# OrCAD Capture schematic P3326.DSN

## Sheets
1 03_Front Camera Connector: size Custom
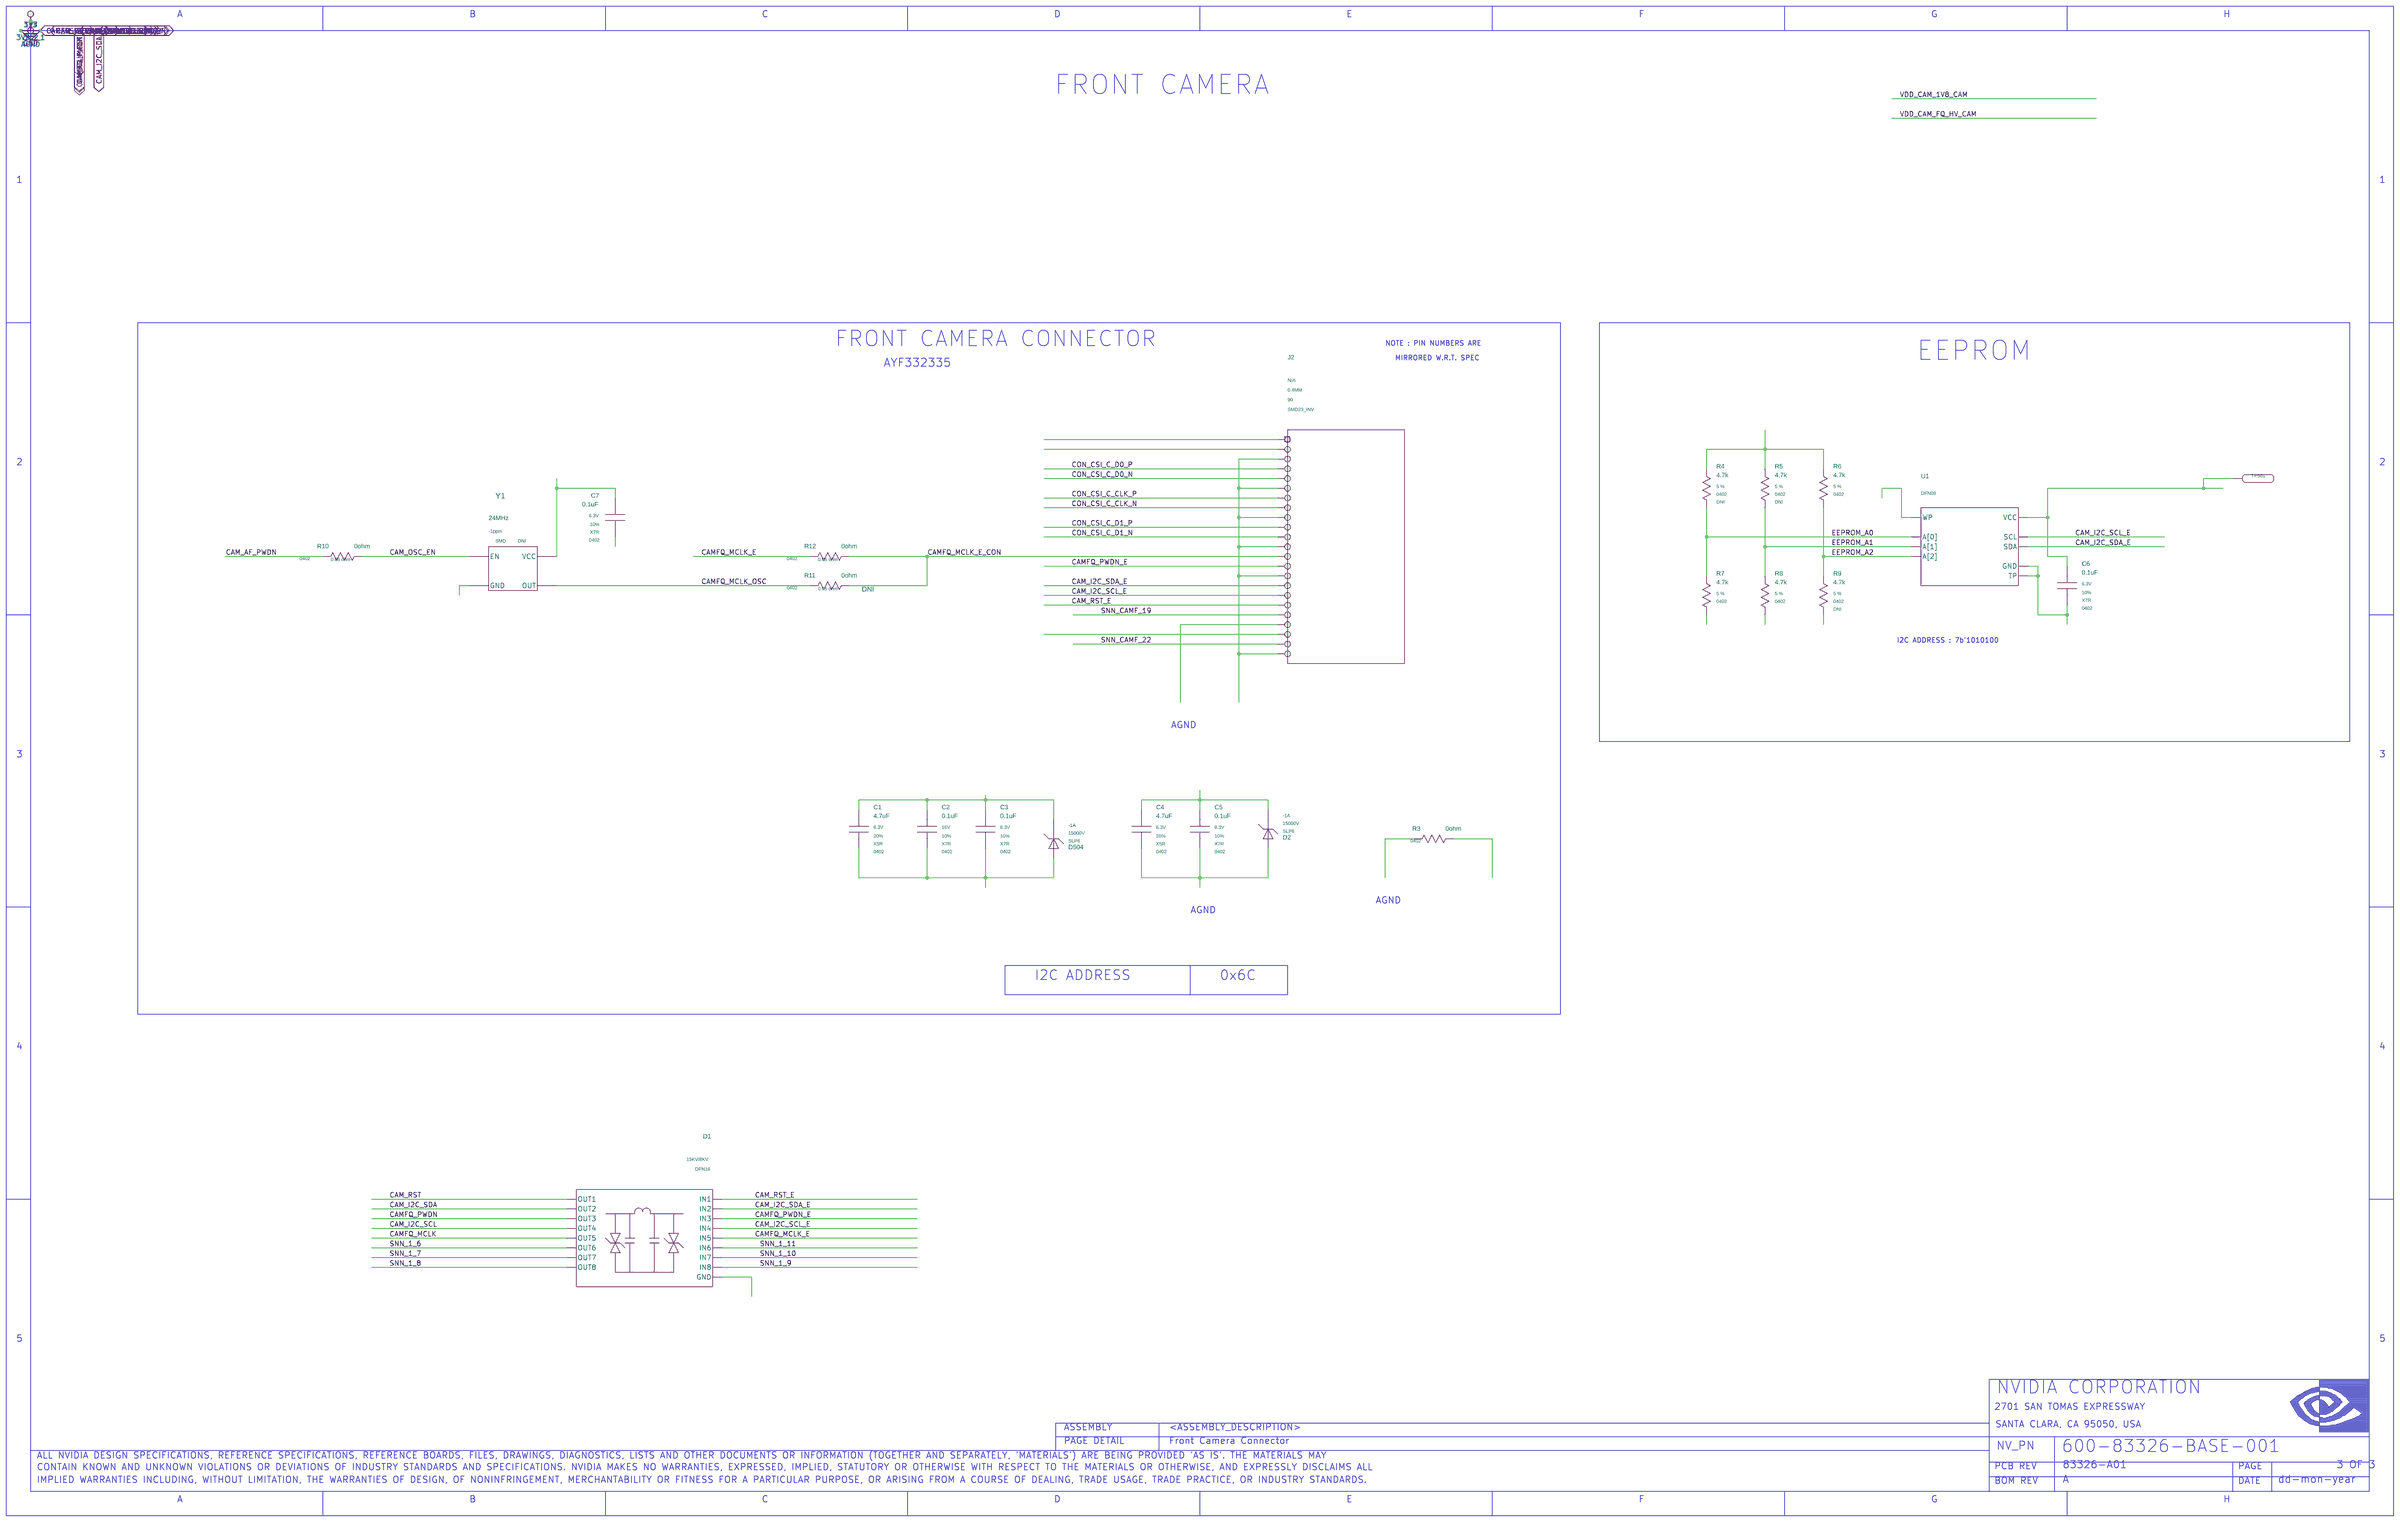
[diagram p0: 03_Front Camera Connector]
2 02_BTB Connector: size Custom
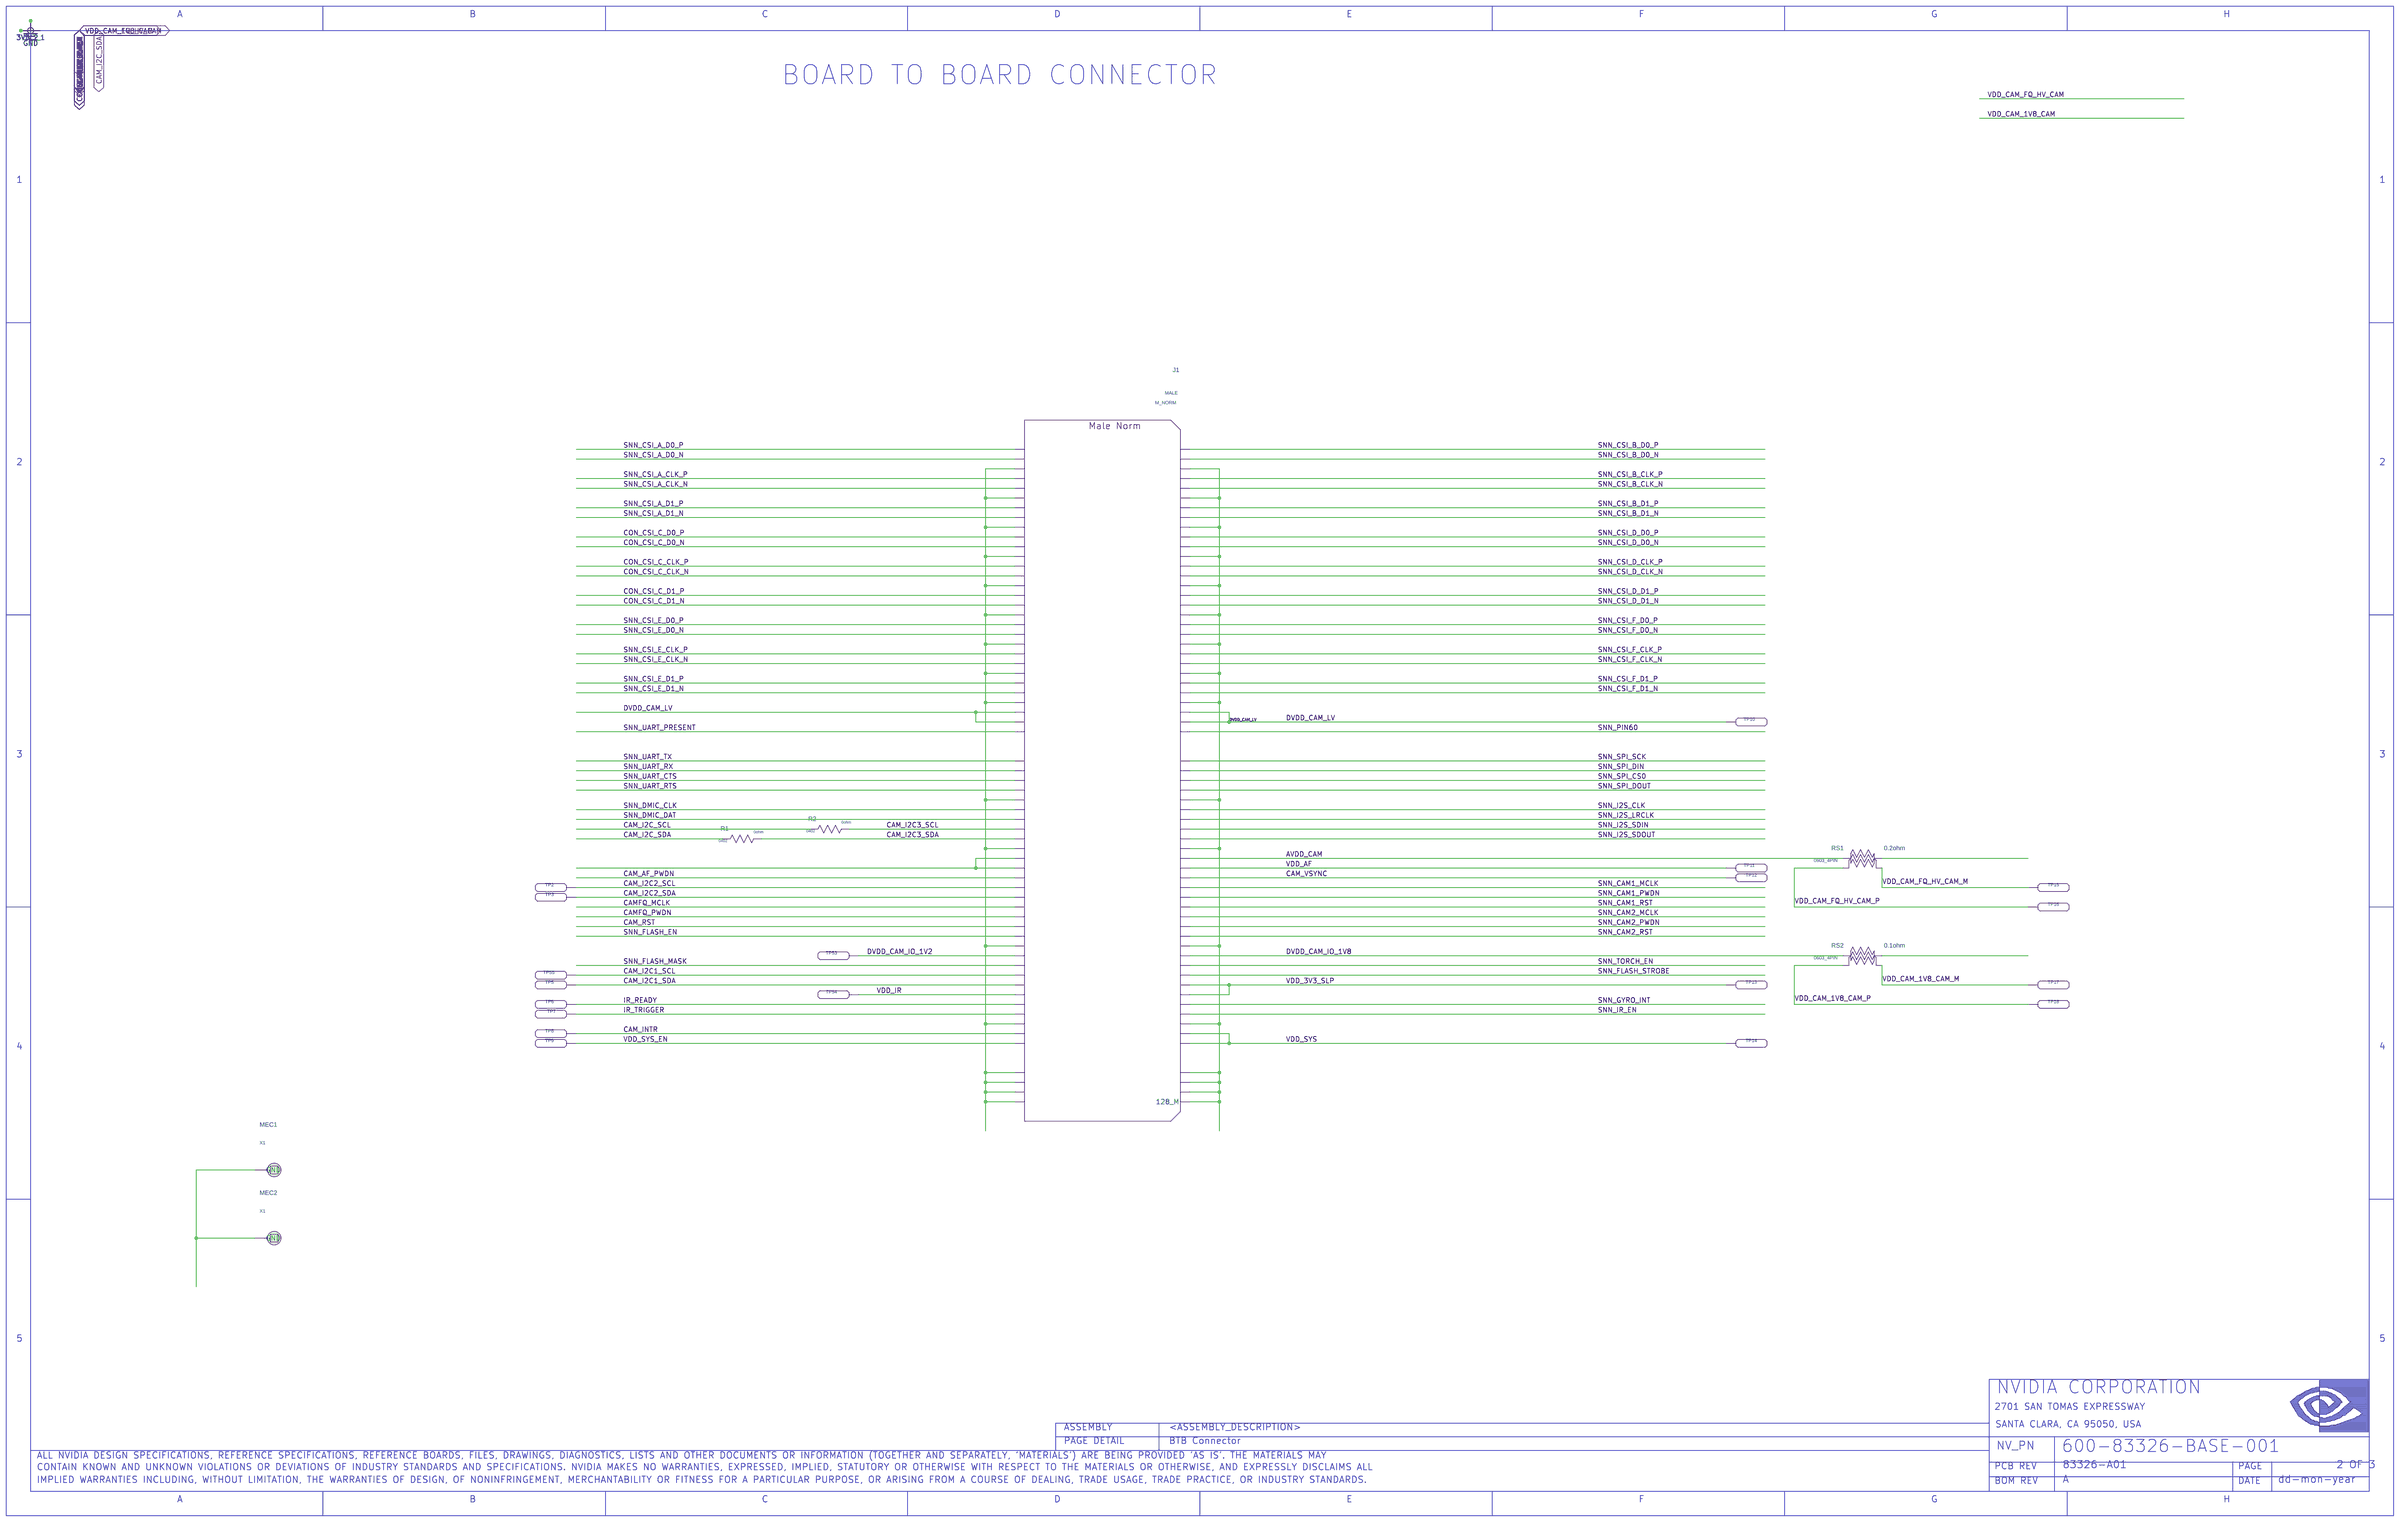
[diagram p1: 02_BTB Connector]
3 01_Table of Contents
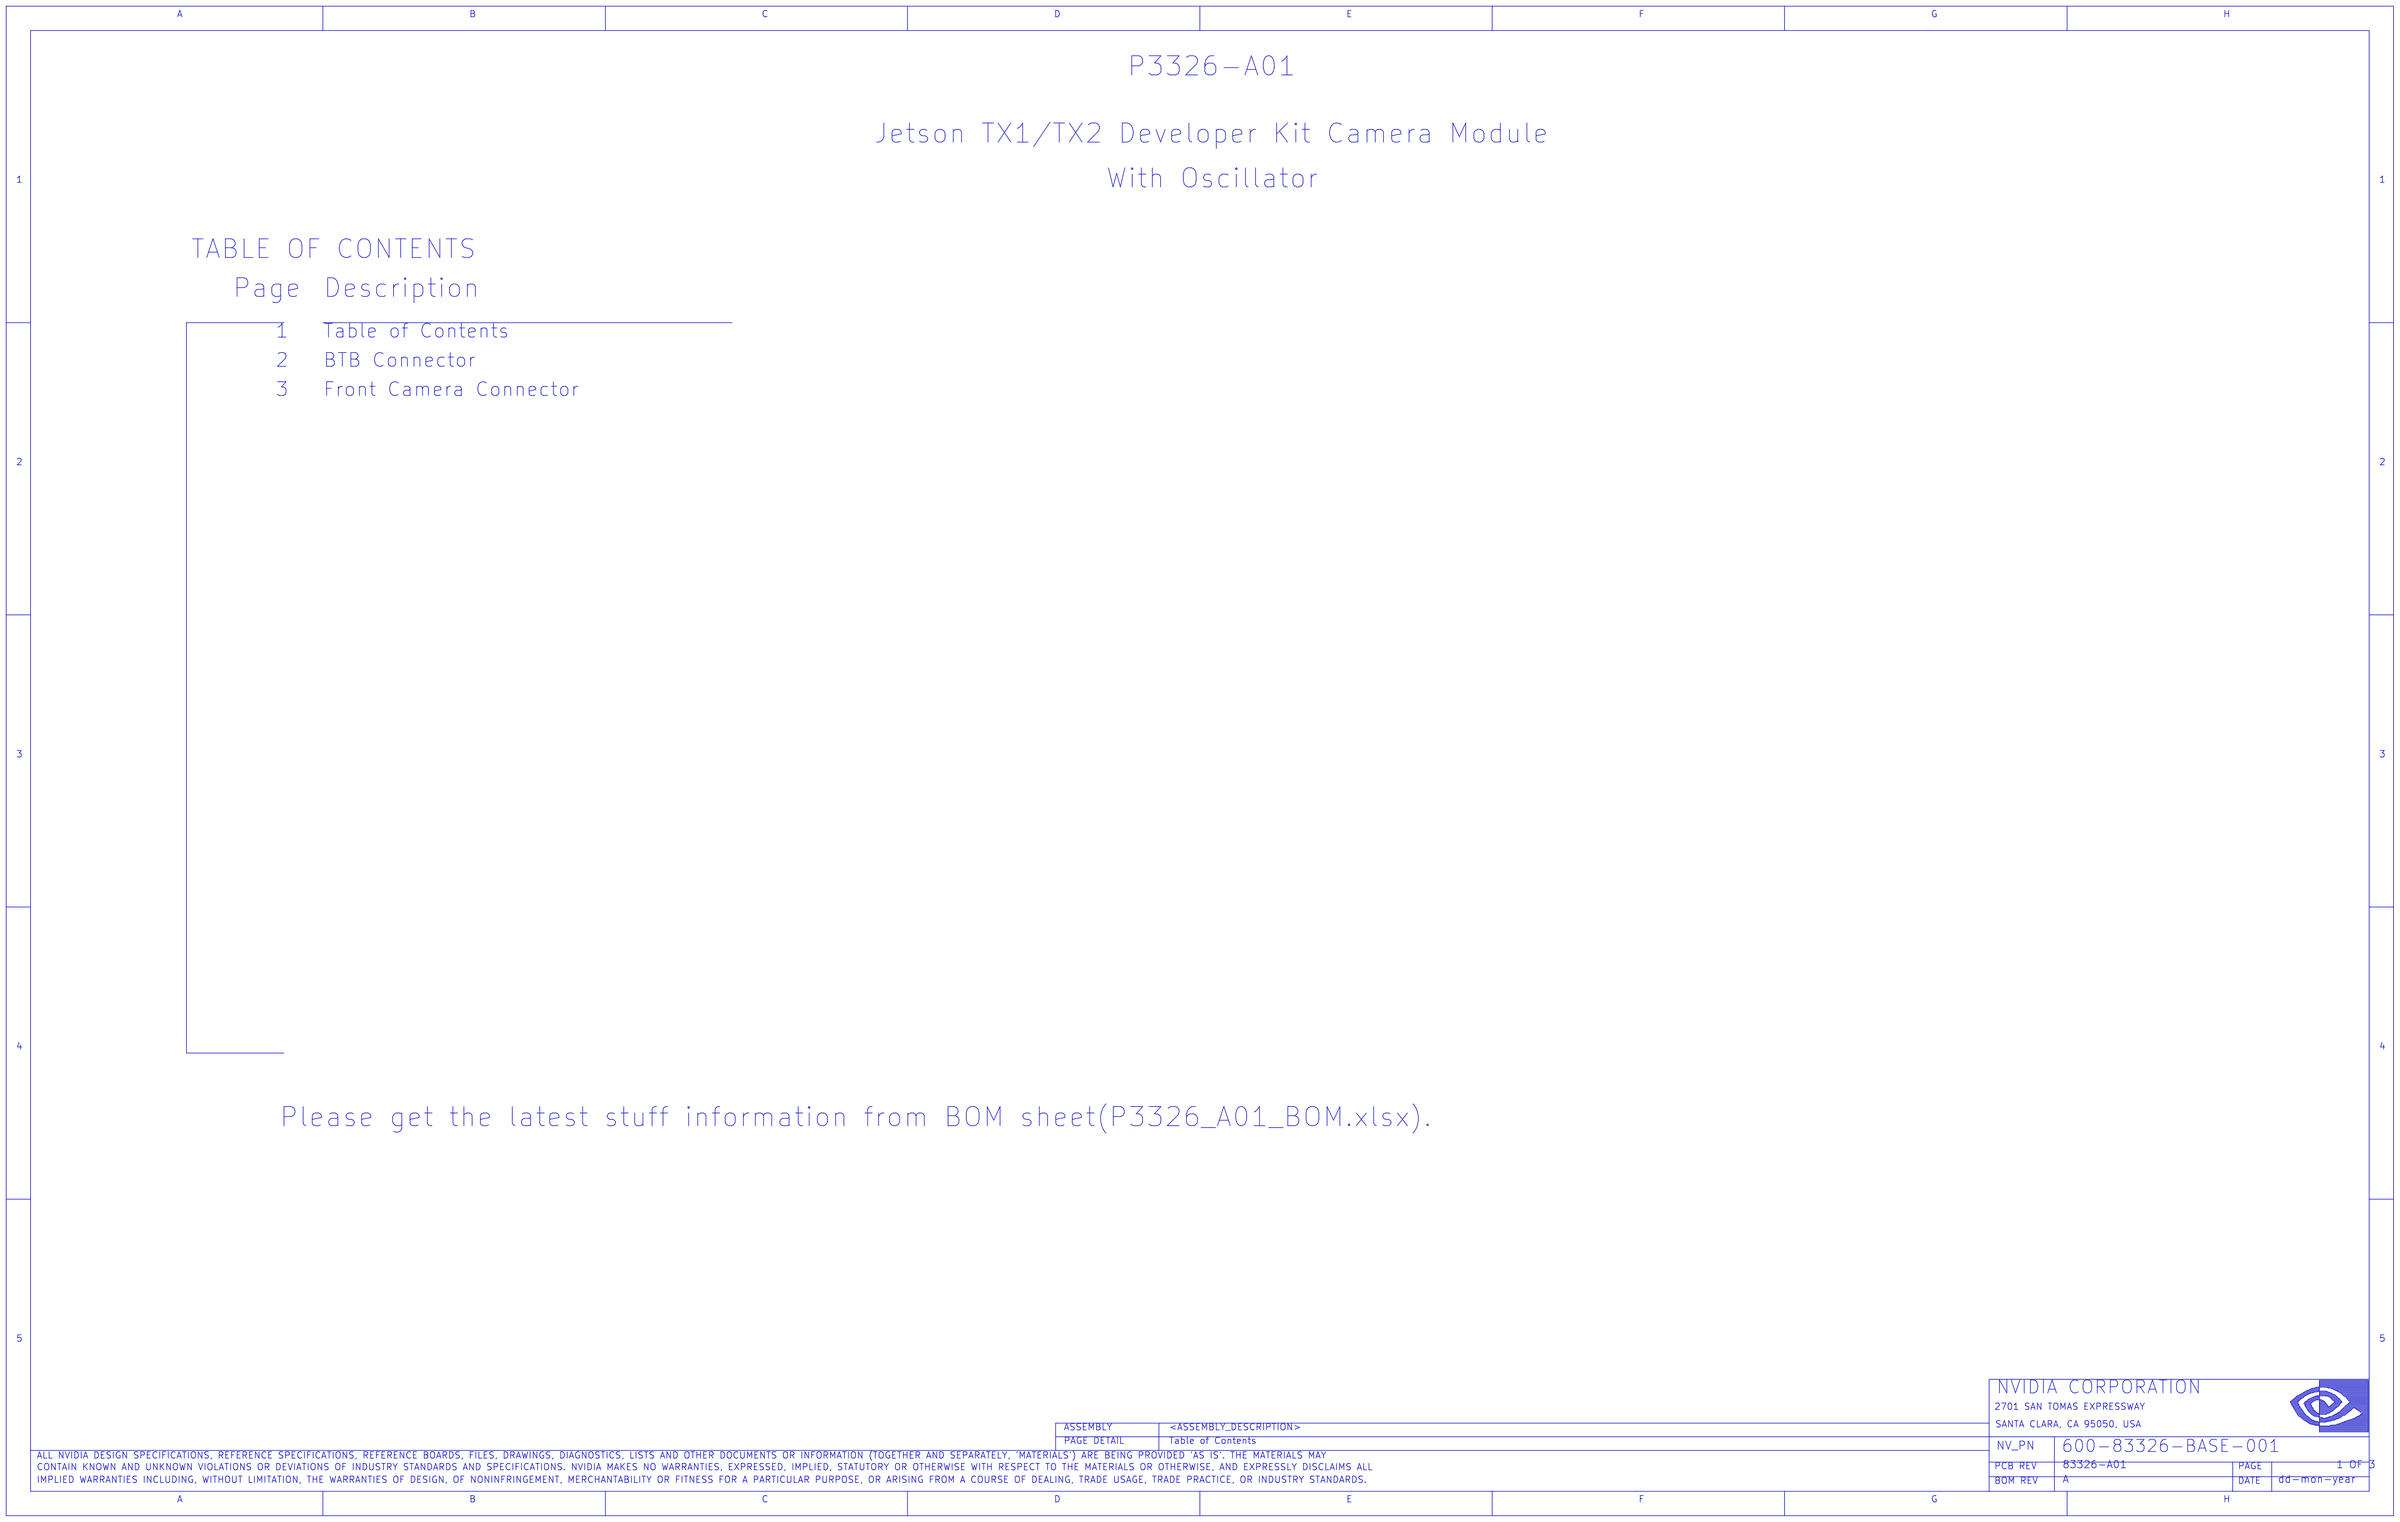
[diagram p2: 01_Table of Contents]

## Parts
sheet 02_BTB Connector
J1  CON_B2B_120  [CON_QTH_120_SMT_ST_P005]
MEC1  MOUNTING_HOLE  [MEC_HOLE_PTH_599C_INT422C_B701C320P]
MEC2  MOUNTING_HOLE  [MEC_HOLE_PTH_599C_INT422C_B701C320P]
R1  0ohm  [0402]
R2  0ohm  [0402]
RS1  0.2ohm  [RES_04_SMD_016X008]
RS2  0.1ohm  [RES_04_SMD_016X008]
TP2  LABTESTPOINT  [LTPT28C49P]
TP3  LABTESTPOINT  [LTPT28C49P]
TP5  LABTESTPOINT  [LTPT28C49P]
TP6  LABTESTPOINT  [LTPT28C49P]
TP7  LABTESTPOINT  [LTPT28C49P]
TP8  LABTESTPOINT  [LTPT28C49P]
TP9  LABTESTPOINT  [LTPT28C49P]
TP10  LABTESTPOINT  [LTPT28C49P]
TP11  LABTESTPOINT  [LTPT28C49P]
TP12  LABTESTPOINT  [LTPT28C49P]
TP13  LABTESTPOINT  [LTPT28C49P]
TP14  LABTESTPOINT  [LTPT28C49P]
TP15  LABTESTPOINT  [LTPT35C49P]
TP16  LABTESTPOINT  [LTPT35C49P]
TP17  LABTESTPOINT  [LTPT35C49P]
TP18  LABTESTPOINT  [LTPT35C49P]
TP53  LABTESTPOINT  [LTPT28C49P]
TP54  LABTESTPOINT  [LTPT28C49P]
TP55  LABTESTPOINT  [LTPT28C49P]
sheet 03_Front Camera Connector
C1  4.7uF  [0402]
C2  0.1uF  [0402]
C3  0.1uF  [0402]
C4  4.7uF  [0402]
C5  0.1uF  [0402]
C6  0.1uF  [0402]
C7  0.1uF  [0402]
D1  D_ESD_ECLAMP2398P_L  [DFN16_P050_040X016_TI130X018]
D2  D_ESD  [DIODE_SMD_010X060_B]
D504  D_ESD  [DIODE_SMD_010X060_B]
J2  CON_FPC_23  [CON_FFC_023_SMD_F_RA_P060_ZIF_B]
R3  0ohm  [0402]
R4  4.7k  [0402]
R5  4.7k  [0402]
R6  4.7k  [0402]
R7  4.7k  [0402]
R8  4.7k  [0402]
R9  4.7k  [0402]
R10  0ohm  [0402]
R11  0ohm  [0402]
R12  0ohm  [0402]
TP501  LABTESTPOINT  [LTPT35C49P]
U1  U_MEM_EE_I2C  [DFN08_P050_030X020_T016X014]
Y1  24MHz  [XTAL_SMD_4_032X025]

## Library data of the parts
J1 = CON_B2B_120: ANGLE: 0; CDS_LIB: electro_mechanic; CDS_PART_NAME: CON_B2B_120_M_NORM-CON_QTH_SMT_2X60_P050,MALE,0.5MM,0,YES,NO,NO,NO,NO,125VAC,1A,080-0025-000; CDS_PHYS_PART_NAME: CON_B2B_120_M_NORM-CON_QTH_SMT_2X60_P050,MALE,0.5MM,0,YES,NO,NO,NO,NO,125VAC,1A,080-0025-000-080-0025-000; CDS_SEC: 1; DEVICE_TYPENAME: CON_B2B_120_M_NORM-CON_QTH_SMT_2X60_P050MALE05MM0YESNONONONO125VAC1A080-0025-000-080-0025-000; DRAWING: @P3326_A01_LIB.P3326_A01(SCH_1):PAGE2; EMI_GROUND_TAB: NO; GENDER: MALE; LATCHING: NO; MAX_CURRENT: 1A; MAX_VOLTAGE: 125VAC; NV_PN: 080-0025-000; PACK_TYPE: M_NORM; PATH: I174; PHYS_PAGE: 2; PITCH: 0.5MM; REFLOW: YES; ROT: 2; SEC: 1; SEC_TYPE: M_NORM; SHIELDED: NO; SHROUDED: NO; VER: 2; XY: (-6500,3700)
MEC1 = MOUNTING_HOLE: CDS_LIB: mechanic; CDS_PART_NAME: MOUNTING_HOLE_X1-P1963_MOUNTING_HOLE_3.2; CDS_PHYS_PART_NAME: MOUNTING_HOLE_X1-P1963_MOUNTING_HOLE_3.2; CDS_SEC: 1; DEVICE_TYPENAME: MOUNTING_HOLE_X1-P1963_MOUNTING_HOLE_32; DRAWING: @P3326_A01_LIB.P3326_A01(SCH_1):PAGE2; PACK_TYPE: X1; PATH: I234; PHYS_PAGE: 2; ROT: 0; SEC: 1; SEC_TYPE: X1; VER: 1; XY: (-10750,1650)
MEC2 = MOUNTING_HOLE: CDS_LIB: mechanic; CDS_PART_NAME: MOUNTING_HOLE_X1-P1963_MOUNTING_HOLE_3.2; CDS_PHYS_PART_NAME: MOUNTING_HOLE_X1-P1963_MOUNTING_HOLE_3.2; CDS_SEC: 1; DEVICE_TYPENAME: MOUNTING_HOLE_X1-P1963_MOUNTING_HOLE_32; DRAWING: @P3326_A01_LIB.P3326_A01(SCH_1):PAGE2; PACK_TYPE: X1; PATH: I235; PHYS_PAGE: 2; ROT: 0; SEC: 1; SEC_TYPE: X1; VER: 1; XY: (-10750,1300)
R1 = R: CDS_LIB: discrete; CDS_PART_NAME: R_0402-0OHM,0.05 OHM,63MW,195-1680-000; CDS_PHYS_PART_NAME: R_0402-0OHM,0.05 OHM,63MW,195-1680-000-0OHM,195-1680-000; CDS_SEC: 1; DEVICE_TYPENAME: R_0402-0OHM005OHM63MW195-1680-000-0OHM195-1680-000; DRAWING: @P3326_A01_LIB.P3326_A01(SCH_1):PAGE2; MAX_WATTAGE: 63mW; NV_PN: 195-1680-000; PATH: I200; PHYS_PAGE: 2; ROT: 0; SEC: 1; TOL: 0.05 ohm; VER: 1; XY: (-8350,3350)
R2 = R: CDS_LIB: discrete; CDS_PART_NAME: R_0402-0OHM,0.05 OHM,63MW,195-1680-000; CDS_PHYS_PART_NAME: R_0402-0OHM,0.05 OHM,63MW,195-1680-000-0OHM,195-1680-000; CDS_SEC: 1; DEVICE_TYPENAME: R_0402-0OHM005OHM63MW195-1680-000-0OHM195-1680-000; DRAWING: @P3326_A01_LIB.P3326_A01(SCH_1):PAGE2; MAX_WATTAGE: 63mW; NV_PN: 195-1680-000; PATH: I201; PHYS_PAGE: 2; ROT: 0; SEC: 1; TOL: 0.05 ohm; VER: 1; XY: (-7900,3400)
RS1 = R_SENSE: CDS_LIB: discrete; CDS_PART_NAME: R_SENSE_0603_4PIN-0.2OHM,1%,0.1W,200PPM,215-0119-000; CDS_PHYS_PART_NAME: R_SENSE_0603_4PIN-0.2OHM,1%,0.1W,200PPM,215-0119-000-0.2OHM,215-0119-000; CDS_SEC: 1; DEVICE_TYPENAME: R_SENSE_0603_4PIN-02OHM101W200PPM215-0119-000-02OHM215-0119-000; DRAWING: @P3326_A01_LIB.P3326_A01(SCH_1):PAGE2; MAX_WATTAGE: 0.1W; NV_PN: 215-0119-000; PACK_TYPE: 0603_4PIN; PATH: I224; PHYS_PAGE: 2; ROT: 0; SEC: 1; TEMP_COEF: 200ppm; TOL: 1%; VER: 3; XY: (-2600,3250)
RS2 = R_SENSE: CDS_LIB: discrete; CDS_PART_NAME: R_SENSE_0603_4PIN-0.1OHM,1%,0.1W,[ ],215-0079-000; CDS_PHYS_PART_NAME: R_SENSE_0603_4PIN-0.1OHM,1%,0.1W,[ ],215-0079-000-0.1OHM,215-0079-000; CDS_SEC: 1; DEVICE_TYPENAME: R_SENSE_0603_4PIN-01OHM101W215-0079-000-01OHM215-0079-000; DRAWING: @P3326_A01_LIB.P3326_A01(SCH_1):PAGE2; MAX_WATTAGE: 0.1W; NV_PN: 215-0079-000; PACK_TYPE: 0603_4PIN; PATH: I220; PHYS_PAGE: 2; ROT: 0; SEC: 1; TEMP_COEF: [ ]; TOL: 1%; VER: 3; XY: (-2600,2750)
TP2 = LABTESTPOINT: CDS_LIB: electro_mechanic; CDS_PART_NAME: LABTESTPOINT_B28-LABTESTPOINT; CDS_PHYS_PART_NAME: LABTESTPOINT_B28-LABTESTPOINT; CDS_SEC: 1; DEVICE_TYPENAME: LABTESTPOINT_B28-LABTESTPOINT; DRAWING: @P3326_A01_LIB.P3326_A01(SCH_1):PAGE2; PACK_TYPE: B28; PATH: I176; PHYS_PAGE: 2; ROT: 2; SEC: 1; VER: 3; XY: (-9250,3100)
TP3 = LABTESTPOINT: CDS_LIB: electro_mechanic; CDS_PART_NAME: LABTESTPOINT_B28-LABTESTPOINT; CDS_PHYS_PART_NAME: LABTESTPOINT_B28-LABTESTPOINT; CDS_SEC: 1; DEVICE_TYPENAME: LABTESTPOINT_B28-LABTESTPOINT; DRAWING: @P3326_A01_LIB.P3326_A01(SCH_1):PAGE2; PACK_TYPE: B28; PATH: I177; PHYS_PAGE: 2; ROT: 2; SEC: 1; VER: 3; XY: (-9250,3050)
TP5 = LABTESTPOINT: CDS_LIB: electro_mechanic; CDS_PART_NAME: LABTESTPOINT_B28-LABTESTPOINT; CDS_PHYS_PART_NAME: LABTESTPOINT_B28-LABTESTPOINT; CDS_SEC: 1; DEVICE_TYPENAME: LABTESTPOINT_B28-LABTESTPOINT; DRAWING: @P3326_A01_LIB.P3326_A01(SCH_1):PAGE2; PACK_TYPE: B28; PATH: I164; PHYS_PAGE: 2; ROT: 2; SEC: 1; VER: 3; XY: (-9250,2600)
TP6 = LABTESTPOINT: CDS_LIB: electro_mechanic; CDS_PART_NAME: LABTESTPOINT_B28-LABTESTPOINT; CDS_PHYS_PART_NAME: LABTESTPOINT_B28-LABTESTPOINT; CDS_SEC: 1; DEVICE_TYPENAME: LABTESTPOINT_B28-LABTESTPOINT; DRAWING: @P3326_A01_LIB.P3326_A01(SCH_1):PAGE2; PACK_TYPE: B28; PATH: I165; PHYS_PAGE: 2; ROT: 2; SEC: 1; VER: 3; XY: (-9250,2500)
TP7 = LABTESTPOINT#1: CDS_LIB: electro_mechanic; CDS_PART_NAME: LABTESTPOINT_B28-LABTESTPOINT; CDS_PHYS_PART_NAME: LABTESTPOINT_B28-LABTESTPOINT; CDS_SEC: 1; DEVICE_TYPENAME: LABTESTPOINT_B28-LABTESTPOINT; DRAWING: @P3326_A01_LIB.P3326_A01(SCH_1):PAGE2; PACK_TYPE: B28; PATH: I166; PHYS_PAGE: 2; ROT: 0; SEC: 1; VER: 1; XY: (-9250,2450)
TP8 = LABTESTPOINT: CDS_LIB: electro_mechanic; CDS_PART_NAME: LABTESTPOINT_B28-LABTESTPOINT; CDS_PHYS_PART_NAME: LABTESTPOINT_B28-LABTESTPOINT; CDS_SEC: 1; DEVICE_TYPENAME: LABTESTPOINT_B28-LABTESTPOINT; DRAWING: @P3326_A01_LIB.P3326_A01(SCH_1):PAGE2; PACK_TYPE: B28; PATH: I163; PHYS_PAGE: 2; ROT: 2; SEC: 1; VER: 3; XY: (-9250,2350)
TP9 = LABTESTPOINT: CDS_LIB: electro_mechanic; CDS_PART_NAME: LABTESTPOINT_B28-LABTESTPOINT; CDS_PHYS_PART_NAME: LABTESTPOINT_B28-LABTESTPOINT; CDS_SEC: 1; DEVICE_TYPENAME: LABTESTPOINT_B28-LABTESTPOINT; DRAWING: @P3326_A01_LIB.P3326_A01(SCH_1):PAGE2; PACK_TYPE: B28; PATH: I225; PHYS_PAGE: 2; ROT: 2; SEC: 1; VER: 3; XY: (-9250,2300)
TP10 = LABTESTPOINT#1: CDS_LIB: electro_mechanic; CDS_PART_NAME: LABTESTPOINT_B28-LABTESTPOINT; CDS_PHYS_PART_NAME: LABTESTPOINT_B28-LABTESTPOINT; CDS_SEC: 1; DEVICE_TYPENAME: LABTESTPOINT_B28-LABTESTPOINT; DRAWING: @P3326_A01_LIB.P3326_A01(SCH_1):PAGE2; PACK_TYPE: B28; PATH: I213; PHYS_PAGE: 2; ROT: 2; SEC: 1; VER: 1; XY: (-3250,3950)
TP11 = LABTESTPOINT#1: CDS_LIB: electro_mechanic; CDS_PART_NAME: LABTESTPOINT_B28-LABTESTPOINT; CDS_PHYS_PART_NAME: LABTESTPOINT_B28-LABTESTPOINT; CDS_SEC: 1; DEVICE_TYPENAME: LABTESTPOINT_B28-LABTESTPOINT; DRAWING: @P3326_A01_LIB.P3326_A01(SCH_1):PAGE2; PACK_TYPE: B28; PATH: I212; PHYS_PAGE: 2; ROT: 2; SEC: 1; VER: 1; XY: (-3250,3200)
TP12 = LABTESTPOINT: CDS_LIB: electro_mechanic; CDS_PART_NAME: LABTESTPOINT_B28-LABTESTPOINT; CDS_PHYS_PART_NAME: LABTESTPOINT_B28-LABTESTPOINT; CDS_SEC: 1; DEVICE_TYPENAME: LABTESTPOINT_B28-LABTESTPOINT; DRAWING: @P3326_A01_LIB.P3326_A01(SCH_1):PAGE2; PACK_TYPE: B28; PATH: I216; PHYS_PAGE: 2; ROT: 0; SEC: 1; VER: 3; XY: (-3250,3150)
TP13 = LABTESTPOINT: CDS_LIB: electro_mechanic; CDS_PART_NAME: LABTESTPOINT_B28-LABTESTPOINT; CDS_PHYS_PART_NAME: LABTESTPOINT_B28-LABTESTPOINT; CDS_SEC: 1; DEVICE_TYPENAME: LABTESTPOINT_B28-LABTESTPOINT; DRAWING: @P3326_A01_LIB.P3326_A01(SCH_1):PAGE2; PACK_TYPE: B28; PATH: I229; PHYS_PAGE: 2; ROT: 0; SEC: 1; VER: 3; XY: (-3250,2600)
TP14 = LABTESTPOINT: CDS_LIB: electro_mechanic; CDS_PART_NAME: LABTESTPOINT_B28-LABTESTPOINT; CDS_PHYS_PART_NAME: LABTESTPOINT_B28-LABTESTPOINT; CDS_SEC: 1; DEVICE_TYPENAME: LABTESTPOINT_B28-LABTESTPOINT; DRAWING: @P3326_A01_LIB.P3326_A01(SCH_1):PAGE2; PACK_TYPE: B28; PATH: I228; PHYS_PAGE: 2; ROT: 0; SEC: 1; VER: 3; XY: (-3250,2300)
TP15 = LABTESTPOINT: CDS_LIB: electro_mechanic; CDS_PART_NAME: LABTESTPOINT_PIN-LABTESTPOINT; CDS_PHYS_PART_NAME: LABTESTPOINT_PIN-LABTESTPOINT; CDS_SEC: 1; DEVICE_TYPENAME: LABTESTPOINT_PIN-LABTESTPOINT; DRAWING: @P3326_A01_LIB.P3326_A01(SCH_1):PAGE2; PACK_TYPE: PIN; PATH: I221; PHYS_PAGE: 2; ROT: 0; SEC: 1; VER: 3; XY: (-1700,3100)
TP16 = LABTESTPOINT: CDS_LIB: electro_mechanic; CDS_PART_NAME: LABTESTPOINT_PIN-LABTESTPOINT; CDS_PHYS_PART_NAME: LABTESTPOINT_PIN-LABTESTPOINT; CDS_SEC: 1; DEVICE_TYPENAME: LABTESTPOINT_PIN-LABTESTPOINT; DRAWING: @P3326_A01_LIB.P3326_A01(SCH_1):PAGE2; PACK_TYPE: PIN; PATH: I222; PHYS_PAGE: 2; ROT: 0; SEC: 1; VER: 3; XY: (-1700,3000)
TP17 = LABTESTPOINT: CDS_LIB: electro_mechanic; CDS_PART_NAME: LABTESTPOINT_PIN-LABTESTPOINT; CDS_PHYS_PART_NAME: LABTESTPOINT_PIN-LABTESTPOINT; CDS_SEC: 1; DEVICE_TYPENAME: LABTESTPOINT_PIN-LABTESTPOINT; DRAWING: @P3326_A01_LIB.P3326_A01(SCH_1):PAGE2; PACK_TYPE: PIN; PATH: I217; PHYS_PAGE: 2; ROT: 0; SEC: 1; VER: 3; XY: (-1700,2600)
TP18 = LABTESTPOINT: CDS_LIB: electro_mechanic; CDS_PART_NAME: LABTESTPOINT_PIN-LABTESTPOINT; CDS_PHYS_PART_NAME: LABTESTPOINT_PIN-LABTESTPOINT; CDS_SEC: 1; DEVICE_TYPENAME: LABTESTPOINT_PIN-LABTESTPOINT; DRAWING: @P3326_A01_LIB.P3326_A01(SCH_1):PAGE2; PACK_TYPE: PIN; PATH: I218; PHYS_PAGE: 2; ROT: 0; SEC: 1; VER: 3; XY: (-1700,2500)
TP53 = LABTESTPOINT: CDS_LIB: electro_mechanic; CDS_PART_NAME: LABTESTPOINT_B28-LABTESTPOINT; CDS_PHYS_PART_NAME: LABTESTPOINT_B28-LABTESTPOINT; CDS_SEC: 1; DEVICE_TYPENAME: LABTESTPOINT_B28-LABTESTPOINT; DRAWING: @P3326_A01_LIB.P3326_A01(SCH_1):PAGE2; PACK_TYPE: B28; PATH: I171; PHYS_PAGE: 2; ROT: 2; SEC: 1; VER: 3; XY: (-7800,2750)
TP54 = LABTESTPOINT: CDS_LIB: electro_mechanic; CDS_PART_NAME: LABTESTPOINT_B28-LABTESTPOINT; CDS_PHYS_PART_NAME: LABTESTPOINT_B28-LABTESTPOINT; CDS_SEC: 1; DEVICE_TYPENAME: LABTESTPOINT_B28-LABTESTPOINT; DRAWING: @P3326_A01_LIB.P3326_A01(SCH_1):PAGE2; PACK_TYPE: B28; PATH: I172; PHYS_PAGE: 2; ROT: 2; SEC: 1; VER: 3; XY: (-7800,2550)
TP55 = LABTESTPOINT: CDS_LIB: electro_mechanic; CDS_PART_NAME: LABTESTPOINT_B28-LABTESTPOINT; CDS_PHYS_PART_NAME: LABTESTPOINT_B28-LABTESTPOINT; CDS_SEC: 1; DEVICE_TYPENAME: LABTESTPOINT_B28-LABTESTPOINT; DRAWING: @P3326_A01_LIB.P3326_A01(SCH_1):PAGE2; PACK_TYPE: B28; PATH: I167; PHYS_PAGE: 2; ROT: 2; SEC: 1; VER: 3; XY: (-9250,2650)
C1 = C: CDS_LIB: discrete; CDS_PART_NAME: C_0402-4.7UF,X5R,20%,6.3V,032-0153-000; CDS_PHYS_PART_NAME: C_0402-4.7UF,X5R,20%,6.3V,032-0153-000-032-0153-000,4.7UF; CDS_SEC: 1; DEVICE_TYPENAME: C_0402-47UFX5R2063V032-0153-000-032-0153-00047UF; DRAWING: @P3326_A01_LIB.P3326_A01(SCH_1):PAGE3; MAT: X5R; MAX_VOLTAGE: 6.3V; NV_PN: 032-0153-000; PATH: I79; PHYS_PAGE: 3; ROT: 0; SEC: 1; TOL: 20%; VER: 1; XY: (-7750,3400)
C2 = C: CDS_LIB: discrete; CDS_PART_NAME: C_0402-0.1UF,X7R,10%,16V,036-0014-000; CDS_PHYS_PART_NAME: C_0402-0.1UF,X7R,10%,16V,036-0014-000-0.1UF,036-0014-000; CDS_SEC: 1; DEVICE_TYPENAME: C_0402-01UFX7R1016V036-0014-000-01UF036-0014-000; DRAWING: @P3326_A01_LIB.P3326_A01(SCH_1):PAGE3; MAT: X7R; MAX_VOLTAGE: 16V; NV_PN: 036-0014-000; PATH: I77; PHYS_PAGE: 3; ROT: 0; SEC: 1; TOL: 10%; VER: 1; XY: (-7400,3400)
C3 = C: CDS_LIB: discrete; CDS_PART_NAME: C_0402-0.1UF,X7R,10%,6.3V,036-0007-000; CDS_PHYS_PART_NAME: C_0402-0.1UF,X7R,10%,6.3V,036-0007-000-0.1UF,036-0007-000; CDS_SEC: 1; DEVICE_TYPENAME: C_0402-01UFX7R1063V036-0007-000-01UF036-0007-000; DRAWING: @P3326_A01_LIB.P3326_A01(SCH_1):PAGE3; MAT: X7R; MAX_VOLTAGE: 6.3V; NV_PN: 036-0007-000; PATH: I66; PHYS_PAGE: 3; ROT: 0; SEC: 1; TOL: 10%; VER: 1; XY: (-7100,3400)
C4 = C: CDS_LIB: discrete; CDS_PART_NAME: C_0402-4.7UF,X5R,20%,6.3V,032-0153-000; CDS_PHYS_PART_NAME: C_0402-4.7UF,X5R,20%,6.3V,032-0153-000-032-0153-000,4.7UF; CDS_SEC: 1; DEVICE_TYPENAME: C_0402-47UFX5R2063V032-0153-000-032-0153-00047UF; DRAWING: @P3326_A01_LIB.P3326_A01(SCH_1):PAGE3; MAT: X5R; MAX_VOLTAGE: 6.3V; NV_PN: 032-0153-000; PATH: I82; PHYS_PAGE: 3; ROT: 0; SEC: 1; TOL: 20%; VER: 1; XY: (-6300,3400)
C5 = C: CDS_LIB: discrete; CDS_PART_NAME: C_0402-0.1UF,X7R,10%,6.3V,036-0007-000; CDS_PHYS_PART_NAME: C_0402-0.1UF,X7R,10%,6.3V,036-0007-000-0.1UF,036-0007-000; CDS_SEC: 1; DEVICE_TYPENAME: C_0402-01UFX7R1063V036-0007-000-01UF036-0007-000; DRAWING: @P3326_A01_LIB.P3326_A01(SCH_1):PAGE3; MAT: X7R; MAX_VOLTAGE: 6.3V; NV_PN: 036-0007-000; PATH: I67; PHYS_PAGE: 3; ROT: 0; SEC: 1; TOL: 10%; VER: 1; XY: (-6000,3400)
C6 = C: CDS_LIB: discrete; CDS_PART_NAME: C_0402-0.1UF,X7R,10%,6.3V,036-0007-000; CDS_PHYS_PART_NAME: C_0402-0.1UF,X7R,10%,6.3V,036-0007-000-0.1UF,036-0007-000; CDS_SEC: 1; DEVICE_TYPENAME: C_0402-01UFX7R1063V036-0007-000-01UF036-0007-000; DRAWING: @P3326_A01_LIB.P3326_A01(SCH_1):PAGE3; MAT: X7R; MAX_VOLTAGE: 6.3V; NV_PN: 036-0007-000; PATH: I54; PHYS_PAGE: 3; ROT: 0; SEC: 1; TOL: 10%; VER: 1; XY: (-1550,4650)
C7 = C: CDS_LIB: discrete; CDS_PART_NAME: C_0402-0.1UF,X7R,10%,6.3V,036-0007-000; CDS_PHYS_PART_NAME: C_0402-0.1UF,X7R,10%,6.3V,036-0007-000-0.1UF,036-0007-000; CDS_SEC: 1; DEVICE_TYPENAME: C_0402-01UFX7R1063V036-0007-000-01UF036-0007-000; DRAWING: @P3326_A01_LIB.P3326_A01(SCH_1):PAGE3; MAT: X7R; MAX_VOLTAGE: 6.3V; NV_PN: 036-0007-000; PATH: I122; PHYS_PAGE: 3; ROT: 2; SEC: 1; TOL: 10%; VER: 1; XY: (-9000,5000)
D1 = D_ESD_ECLAMP2398P_L: CDS_LIB: p3326_a01_lib; CDS_PART_NAME: D_ESD_ECLAMP2398P_L_DFN16-ECLAMP2398P.TCT,15KV/8KV,N/A,0.95V @ 0.01A,N/A,101-0075-000; CDS_PHYS_PART_NAME: D_ESD_ECLAMP2398P_L_DFN16-ECLAMP2398P.TCT,15KV/8KV,N/A,0.95V @ 0.01A,N/A,101-0075-000-101-0075-000; CDS_SEC: 1; CONTINUOUS_CURRENT: N/A; DEVICE_TYPENAME: D_ESD_ECLAMP2398P_L_DFN16-ECLAMP2398PTCT15KV8KVNA095V001ANA101-0075-000-101-0075-000; DRAWING: @P3326_A01_LIB.P3326_A01(SCH_1):PAGE3; FORWARD_VOLTAGE: 0.95V @ 0.01A; MAX_CURRENT: N/A; MAX_VOLTAGE: 15KV/8KV; NV_PN: 101-0075-000; PACK_TYPE: DFN16; PATH: I18; PHYS_PAGE: 3; ROT: 2; SEC: 1; VER: 1; XY: (-8850,1200)
D2 = D_ESD: CDS_LIB: discrete; CDS_PART_NAME: D_ESD_SLP6-UCLAMP0501P,2 MUTUALLY OPPOSING SERIES WITH PROTECTION DIODES,15000V,[ ],0.8V@-9.999A,-1A,090-0084-000; CDS_PHYS_PART_NAME: D_ESD_SLP6-UCLAMP0501P,2 MUTUALLY OPPOSING SERIES WITH PROTECTION DIODES,15000V,[ ],0.8V@-9.999A,-1A,090-0084-000-090-0084-000; CDS_SEC: 1; CONFIGURATION: 2 Mutually Opposing Series with Protection Diodes; CONTINUOUS_CURRENT: -1A; DEVICE_TYPENAME: D_ESD_SLP6-UCLAMP0501P2MUTUALLYOPPOSINGSERIESWITHPROTECTIONDIODES15000V08V-9999A-1A090-0084-000-090-0084-000; DRAWING: @P3326_A01_LIB.P3326_A01(SCH_1):PAGE3; FORWARD_VOLTAGE: 0.8V@-9.999A; MAX_CURRENT: [ ]; MAX_VOLTAGE: 15000V; NV_PN: 090-0084-000; PACK_TYPE: SLP6; PATH: I75; PHYS_PAGE: 3; ROT: 6; SEC: 1; VER: 4; XY: (-5650,3400)
D504 = D_ESD: CDS_LIB: discrete; CDS_PART_NAME: D_ESD_SLP6-UCLAMP0501P,2 MUTUALLY OPPOSING SERIES WITH PROTECTION DIODES,15000V,[ ],0.8V@-9.999A,-1A,090-0084-000; CDS_PHYS_PART_NAME: D_ESD_SLP6-UCLAMP0501P,2 MUTUALLY OPPOSING SERIES WITH PROTECTION DIODES,15000V,[ ],0.8V@-9.999A,-1A,090-0084-000-090-0084-000; CDS_SEC: 1; CONFIGURATION: 2 Mutually Opposing Series with Protection Diodes; CONTINUOUS_CURRENT: -1A; DEVICE_TYPENAME: D_ESD_SLP6-UCLAMP0501P2MUTUALLYOPPOSINGSERIESWITHPROTECTIONDIODES15000V08V-9999A-1A090-0084-000-090-0084-000; DRAWING: @P3326_A01_LIB.P3326_A01(SCH_1):PAGE3; FORWARD_VOLTAGE: 0.8V@-9.999A; MAX_CURRENT: [ ]; MAX_VOLTAGE: 15000V; NV_PN: 090-0084-000; PACK_TYPE: SLP6; PATH: I74; PHYS_PAGE: 3; ROT: 6; SEC: 1; VER: 4; XY: (-6750,3350)
J2 = CON_FPC_23: ANGLE: 90; CDS_LIB: electro_mechanic; CDS_PART_NAME: CON_FPC_23_SMD23_INV-AYF332335,N/A,0.4MM,90,YES,YES,NO,NO,NO,50V,0.2A,080-0498-000; CDS_PHYS_PART_NAME: CON_FPC_23_SMD23_INV-AYF332335,N/A,0.4MM,90,YES,YES,NO,NO,NO,50V,0.2A,080-0498-000-080-0498-000; CDS_SEC: 1; DEVICE_TYPENAME: CON_FPC_23_SMD23_INV-AYF332335NA04MM90YESYESNONONO50V02A080-0498-000-080-0498-000; DRAWING: @P3326_A01_LIB.P3326_A01(SCH_1):PAGE3; EMI_GROUND_TAB: NO; GENDER: N/A; LATCHING: NO; MAX_CURRENT: 0.2A; MAX_VOLTAGE: 50V; NV_PN: 080-0498-000; PACK_TYPE: SMD23_INV; PATH: I109; PHYS_PAGE: 3; PITCH: 0.4MM; REFLOW: YES; ROT: 0; SEC: 1; SHIELDED: No; SHROUDED: yes; VER: 3; XY: (-5250,4850)
R3 = R: CDS_LIB: discrete; CDS_PART_NAME: R_0402-0OHM,0.05 OHM,62.5MW,195-2655-000; CDS_PHYS_PART_NAME: R_0402-0OHM,0.05 OHM,62.5MW,195-2655-000-0OHM,195-2655-000; CDS_SEC: 1; DEVICE_TYPENAME: R_0402-0OHM005OHM625MW195-2655-000-0OHM195-2655-000; DRAWING: @P3326_A01_LIB.P3326_A01(SCH_1):PAGE3; MAX_WATTAGE: 62.5mW; NV_PN: 195-2655-000; PATH: I73; PHYS_PAGE: 3; ROT: 0; SEC: 1; TOL: 0.05 ohm; VER: 1; XY: (-4800,3350)
R4 = R#1: CDS_LIB: discrete; CDS_PART_NAME: R_0402-4.7K,5 %,62.5MW,195-0598-000; CDS_PHYS_PART_NAME: R_0402-4.7K,5 %,62.5MW,195-0598-000-195-0598-000,4.7K; CDS_SEC: 1; CHIPS_PART_NAME: R; DEVICE_TYPENAME: R_0402-47K5625MW195-0598-000-195-0598-00047K; DRAWING: @P3326_A01_LIB.P3326_A01(SCH_1):PAGE3; MAX_WATTAGE: 62.5mW; NV_PN: 195-0598-000; PATH: I44; PHYS_PAGE: 3; ROT: 0; SEC: 1; SKU: DNI; TOL: 5 %; VER: 2; XY: (-3400,5150)
R5 = R#1: CDS_LIB: discrete; CDS_PART_NAME: R_0402-4.7K,5 %,62.5MW,195-0598-000; CDS_PHYS_PART_NAME: R_0402-4.7K,5 %,62.5MW,195-0598-000-195-0598-000,4.7K; CDS_SEC: 1; CHIPS_PART_NAME: R; DEVICE_TYPENAME: R_0402-47K5625MW195-0598-000-195-0598-00047K; DRAWING: @P3326_A01_LIB.P3326_A01(SCH_1):PAGE3; MAX_WATTAGE: 62.5mW; NV_PN: 195-0598-000; PATH: I46; PHYS_PAGE: 3; ROT: 0; SEC: 1; SKU: DNI; TOL: 5 %; VER: 2; XY: (-3100,5150)
R6 = R#1: CDS_LIB: discrete; CDS_PART_NAME: R_0402-4.7K,5 %,62.5MW,195-0598-000; CDS_PHYS_PART_NAME: R_0402-4.7K,5 %,62.5MW,195-0598-000-195-0598-000,4.7K; CDS_SEC: 1; CHIPS_PART_NAME: R; DEVICE_TYPENAME: R_0402-47K5625MW195-0598-000-195-0598-00047K; DRAWING: @P3326_A01_LIB.P3326_A01(SCH_1):PAGE3; MAX_WATTAGE: 62.5mW; NV_PN: 195-0598-000; PATH: I49; PHYS_PAGE: 3; ROT: 0; SEC: 1; TOL: 5 %; VER: 2; XY: (-2800,5150)
R7 = R#1: CDS_LIB: discrete; CDS_PART_NAME: R_0402-4.7K,5 %,62.5MW,195-0598-000; CDS_PHYS_PART_NAME: R_0402-4.7K,5 %,62.5MW,195-0598-000-195-0598-000,4.7K; CDS_SEC: 1; CHIPS_PART_NAME: R; DEVICE_TYPENAME: R_0402-47K5625MW195-0598-000-195-0598-00047K; DRAWING: @P3326_A01_LIB.P3326_A01(SCH_1):PAGE3; MAX_WATTAGE: 62.5mW; NV_PN: 195-0598-000; PATH: I45; PHYS_PAGE: 3; ROT: 0; SEC: 1; TOL: 5 %; VER: 2; XY: (-3400,4600)
R8 = R#1: CDS_LIB: discrete; CDS_PART_NAME: R_0402-4.7K,5 %,62.5MW,195-0598-000; CDS_PHYS_PART_NAME: R_0402-4.7K,5 %,62.5MW,195-0598-000-195-0598-000,4.7K; CDS_SEC: 1; CHIPS_PART_NAME: R; DEVICE_TYPENAME: R_0402-47K5625MW195-0598-000-195-0598-00047K; DRAWING: @P3326_A01_LIB.P3326_A01(SCH_1):PAGE3; MAX_WATTAGE: 62.5mW; NV_PN: 195-0598-000; PATH: I47; PHYS_PAGE: 3; ROT: 0; SEC: 1; TOL: 5 %; VER: 2; XY: (-3100,4600)
R9 = R#1: CDS_LIB: discrete; CDS_PART_NAME: R_0402-4.7K,5 %,62.5MW,195-0598-000; CDS_PHYS_PART_NAME: R_0402-4.7K,5 %,62.5MW,195-0598-000-195-0598-000,4.7K; CDS_SEC: 1; CHIPS_PART_NAME: R; DEVICE_TYPENAME: R_0402-47K5625MW195-0598-000-195-0598-00047K; DRAWING: @P3326_A01_LIB.P3326_A01(SCH_1):PAGE3; MAX_WATTAGE: 62.5mW; NV_PN: 195-0598-000; PATH: I48; PHYS_PAGE: 3; ROT: 0; SEC: 1; SKU: DNI; TOL: 5 %; VER: 2; XY: (-2800,4600)
R10 = R: ASSEMBLY: CAM_CON; CDS_LIB: discrete; CDS_PART_NAME: R_0402-0OHM,0.05 OHM,62.5MW,195-2655-000; CDS_PHYS_PART_NAME: R_0402-0OHM,0.05 OHM,62.5MW,195-2655-000-0OHM,195-2655-000; CDS_SEC: 1; DEVICE_TYPENAME: R_0402-0OHM005OHM625MW195-2655-000-0OHM195-2655-000; DRAWING: @P3326_A01_LIB.P3326_A01(SCH_1):PAGE3; MAX_WATTAGE: 62.5mW; NV_PN: 195-2655-000; PATH: I118; PHYS_PAGE: 3; ROT: 0; SEC: 1; TOL: 0.05 ohm; VER: 1; XY: (-10400,4800)
R11 = R: ASSEMBLY: CAM_CON; CDS_LIB: discrete; CDS_PART_NAME: R_0402-0OHM,0.05 OHM,62.5MW,195-2655-000; CDS_PHYS_PART_NAME: R_0402-0OHM,0.05 OHM,62.5MW,195-2655-000-0OHM,195-2655-000; CDS_SEC: 1; DEVICE_TYPENAME: R_0402-0OHM005OHM625MW195-2655-000-0OHM195-2655-000; DRAWING: @P3326_A01_LIB.P3326_A01(SCH_1):PAGE3; MAX_WATTAGE: 62.5mW; NV_PN: 195-2655-000; PATH: I112; PHYS_PAGE: 3; ROT: 0; SEC: 1; SKU: DNI; TOL: 0.05 ohm; VER: 1; XY: (-7900,4650)
R12 = R: ASSEMBLY: CAM_CON; CDS_LIB: discrete; CDS_PART_NAME: R_0402-0OHM,0.05 OHM,62.5MW,195-2655-000; CDS_PHYS_PART_NAME: R_0402-0OHM,0.05 OHM,62.5MW,195-2655-000-0OHM,195-2655-000; CDS_SEC: 1; DEVICE_TYPENAME: R_0402-0OHM005OHM625MW195-2655-000-0OHM195-2655-000; DRAWING: @P3326_A01_LIB.P3326_A01(SCH_1):PAGE3; MAX_WATTAGE: 62.5mW; NV_PN: 195-2655-000; PATH: I111; PHYS_PAGE: 3; ROT: 0; SEC: 1; TOL: 0.05 ohm; VER: 1; XY: (-7900,4800)
TP501 = LABTESTPOINT: CDS_LIB: electro_mechanic; CDS_PART_NAME: LABTESTPOINT_PIN-LABTESTPOINT; CDS_PHYS_PART_NAME: LABTESTPOINT_PIN-LABTESTPOINT; CDS_SEC: 1; DEVICE_TYPENAME: LABTESTPOINT_PIN-LABTESTPOINT; DRAWING: @P3326_A01_LIB.P3326_A01(SCH_1):PAGE3; PACK_TYPE: PIN; PATH: I62; PHYS_PAGE: 3; ROT: 0; SEC: 1; VER: 3; XY: (-650,5200)
U1 = U_MEM_EE_I2C: CDS_LIB: p3326_a01_lib; CDS_PART_NAME: U_MEM_EE_I2C_DFN08-100KHZ,1.7V..5.5V,CAT24C02HU4IGT3A,174-0133-000; CDS_PHYS_PART_NAME: U_MEM_EE_I2C_DFN08-100KHZ,1.7V..5.5V,CAT24C02HU4IGT3A,174-0133-000-174-0133-000; CDS_SEC: 1; DEVICE_TYPENAME: U_MEM_EE_I2C_DFN08-100KHZ17V55VCAT24C02HU4IGT3A174-0133-000-174-0133-000; DRAWING: @P3326_A01_LIB.P3326_A01(SCH_1):PAGE3; NV_PN: 174-0133-000; PACK_TYPE: DFN08; PATH: I123; PHYS_PAGE: 3; POW: 1.7V..5.5V; ROT: 0; SEC: 1; SPEED_GRADE: 100KHz; VER: 2; XY: (-2050,4850)
Y1 = OSC_4PIN: ASSEMBLY: CAM_CON; CDS_LIB: clocks; CDS_PART_NAME: OSC_4PIN_SMD-DSEC24.0000MNSN,24MHZ,-1PPM,2PPM,100PPM,15PF,086-0085-000; CDS_PHYS_PART_NAME: OSC_4PIN_SMD-DSEC24.0000MNSN,24MHZ,-1PPM,2PPM,100PPM,15PF,086-0085-000-086-0085-000,24MHZ; CDS_SEC: 1; DEVICE_TYPENAME: OSC_4PIN_SMD-DSEC240000MNSN24MHZ-1PPM2PPM100PPM15PF086-0085-000-086-0085-00024MHZ; DRAWING: @P3326_A01_LIB.P3326_A01(SCH_1):PAGE3; LOAD_CAPACITANCE: 15pF; NV_PN: 086-0085-000; PACK_TYPE: SMD; PATH: I113; PHYS_PAGE: 3; ROT: 0; SEC: 1; SKU: DNI; TOL: -1ppm; TOL_AGE: 2ppm; TOL_TOTAL: 100ppm; VER: 1; XY: (-9550,4750)

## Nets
AGND: C4.2 C5.2 D2.1(1A) J2.20 R3.1
AVDD_CAM: J1.82 RS1.1
DVDD_CAM_IO_1V2: J1.101 TP53.1
DVDD_CAM_IO_1V8: J1.102 RS2.1
DVDD_CAM_LV: J1.55 J1.56 J1.57 J1.58 TP10.1
GND: C1.2 C2.2 C3.2 C6.2 C7.2 D1.17(GND) D504.1(1A) J1.5 J1.6 J1.11 J1.12 J1.17 J1.18 J1.23 J1.24 J1.29 J1.30 J1.35 J1.36 J1.41 J1.42 J1.47 J1.48 J1.53 J1.54 J1.69 J1.70 J1.79 J1.80 J1.99 J1.100 J1.115 J1.116 J1.121 J1.122 J1.123 J1.124 J1.125 J1.126 J1.127 J1.128(128_M) J2.3 J2.6 J2.9 J2.12 J2.15 J2.23 MEC1.1(GND) MEC2.1(GND) R3.2 R7.2 R8.2 R9.2 U1.4(GND) U1.7(WP) U1.9(TP) Y1.2(GND)
VDD_3V3_SLP: J1.108 J1.110 TP13.1
VDD_AF: J1.84 TP11.1
VDD_CAM_1V8_CAM: C1.1 C2.1 C3.1 C6.1 C7.1 D504.2(2C) J2.1 J2.2 R4.1 R5.1 R6.1 RS2.4 TP501.1 U1.8(VCC) Y1.4(VCC)
VDD_CAM_1V8_CAM_M: RS2.3 TP17.1
VDD_CAM_1V8_CAM_P: RS2.2 TP18.1
VDD_CAM_FQ_HV_CAM: C4.1 C5.1 D2.2(2C) J1.81 J1.83 J2.21 RS1.4
VDD_CAM_FQ_HV_CAM_M: RS1.3 TP15.1
VDD_CAM_FQ_HV_CAM_P: RS1.2 TP16.1
VDD_IR: J1.109 TP54.1
VDD_SYS: J1.118 J1.120 TP14.1
VDD_SYS_EN: J1.119 TP9.1
CAM_AF_PWDN: J1.85 R10.1
CAM_I2C1_SCL: J1.105 TP55.1
CAM_I2C1_SDA: J1.107 TP5.1
CAM_I2C2_SCL: J1.87 TP2.1
CAM_I2C2_SDA: J1.89 TP3.1
CAM_I2C3_SCL: J1.75 R2.2
CAM_I2C3_SDA: J1.77 R1.2
CAM_I2C_SCL: D1.13(OUT4) R2.1
CAM_I2C_SCL_E: D1.4(IN4) J2.17 U1.6(SCL)
CAM_I2C_SDA: D1.15(OUT2) R1.1
CAM_I2C_SDA_E: D1.2(IN2) J2.16 U1.5(SDA)
CAM_INTR: J1.117 TP8.1
CAM_OSC_EN: R10.2 Y1.1(EN)
CAM_RST: D1.16(OUT1) J1.95
CAM_RST_E: D1.1(IN1) J2.18
CAM_VSYNC: J1.86 TP12.1
CAMFQ_MCLK: D1.12(OUT5) J1.91
CAMFQ_MCLK_E: D1.5(IN5) R12.1
CAMFQ_MCLK_E_CON: J2.13 R11.2 R12.2
CAMFQ_MCLK_OSC: R11.1 Y1.3(OUT)
CAMFQ_PWDN: D1.14(OUT3) J1.93
CAMFQ_PWDN_E: D1.3(IN3) J2.14
CON_CSI_C_CLK_N: J1.27 J2.8
CON_CSI_C_CLK_P: J1.25 J2.7
CON_CSI_C_D0_N: J1.21 J2.5
CON_CSI_C_D0_P: J1.19 J2.4
CON_CSI_C_D1_N: J1.33 J2.11
CON_CSI_C_D1_P: J1.31 J2.10
EEPROM_A0: R4.2 R7.1 U1.1(A[0])
EEPROM_A1: R5.2 R8.1 U1.2(A[1])
EEPROM_A2: R6.2 R9.1 U1.3(A[2])
IR_READY: J1.111 TP6.1
IR_TRIGGER: J1.113 TP7.1
SNN_1_6: D1.11(OUT6)
SNN_1_7: D1.10(OUT7)
SNN_1_8: D1.9(OUT8)
SNN_1_9: D1.8(IN8)
SNN_1_10: D1.7(IN7)
SNN_1_11: D1.6(IN6)
SNN_CAM1_MCLK: J1.88
SNN_CAM1_PWDN: J1.90
SNN_CAM1_RST: J1.92
SNN_CAM2_MCLK: J1.94
SNN_CAM2_PWDN: J1.96
SNN_CAM2_RST: J1.98
SNN_CAMF_19: J2.19
SNN_CAMF_22: J2.22
SNN_CSI_A_CLK_N: J1.9
SNN_CSI_A_CLK_P: J1.7
SNN_CSI_A_D0_N: J1.3
SNN_CSI_A_D0_P: J1.1
SNN_CSI_A_D1_N: J1.15
SNN_CSI_A_D1_P: J1.13
SNN_CSI_B_CLK_N: J1.10
SNN_CSI_B_CLK_P: J1.8
SNN_CSI_B_D0_N: J1.4
SNN_CSI_B_D0_P: J1.2
SNN_CSI_B_D1_N: J1.16
SNN_CSI_B_D1_P: J1.14
SNN_CSI_D_CLK_N: J1.28
SNN_CSI_D_CLK_P: J1.26
SNN_CSI_D_D0_N: J1.22
SNN_CSI_D_D0_P: J1.20
SNN_CSI_D_D1_N: J1.34
SNN_CSI_D_D1_P: J1.32
SNN_CSI_E_CLK_N: J1.45
SNN_CSI_E_CLK_P: J1.43
SNN_CSI_E_D0_N: J1.39
SNN_CSI_E_D0_P: J1.37
SNN_CSI_E_D1_N: J1.51
SNN_CSI_E_D1_P: J1.49
SNN_CSI_F_CLK_N: J1.46
SNN_CSI_F_CLK_P: J1.44
SNN_CSI_F_D0_N: J1.40
SNN_CSI_F_D0_P: J1.38
SNN_CSI_F_D1_N: J1.52
SNN_CSI_F_D1_P: J1.50
SNN_DMIC_CLK: J1.71
SNN_DMIC_DAT: J1.73
SNN_FLASH_EN: J1.97
SNN_FLASH_MASK: J1.103
SNN_FLASH_STROBE: J1.106
SNN_GYRO_INT: J1.112
SNN_I2S_CLK: J1.72
SNN_I2S_LRCLK: J1.74
SNN_I2S_SDIN: J1.76
SNN_I2S_SDOUT: J1.78
SNN_IR_EN: J1.114
SNN_PIN60: J1.60
SNN_SPI_CS0: J1.66
SNN_SPI_DIN: J1.64
SNN_SPI_DOUT: J1.68
SNN_SPI_SCK: J1.62
SNN_TORCH_EN: J1.104
SNN_UART_CTS: J1.65
SNN_UART_PRESENT: J1.59
SNN_UART_RTS: J1.67
SNN_UART_RX: J1.63
SNN_UART_TX: J1.61

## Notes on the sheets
sheet 1
- A
- B
- C
- D
- E
- F
- G
- H
- FRONT CAMERA
- 1
- 1
- FRONT CAMERA CONNECTOR
- NOTE : PIN NUMBERS ARE
- EEPROM
- AYF332335
- MIRRORED W.R.T. SPEC
- 2
- 2
- I2C ADDRESS : 7b'1010100
- AGND
- 3
- 3
- AGND
- AGND
- I2C ADDRESS
- 0x6C
- 4
- 4
- 5
- 5
- NVIDIA CORPORATION
- 2701 SAN TOMAS EXPRESSWAY
- ASSEMBLY
- <ASSEMBLY_DESCRIPTION>
- SANTA CLARA, CA 95050, USA
- PAGE DETAIL
- Front Camera Connector
- NV_PN
- 600-83326-BASE-001
- ALL NVIDIA DESIGN SPECIFICATIONS, REFERENCE SPECIFICATIONS, REFERENCE BOARDS, FILES, DRAWINGS, DIAGNOSTICS, LISTS AND OTHER DOCUMENTS OR INFORMATION (TOGETHER AND SEPARATELY, 'MATERIALS') ARE BEING PROVIDED 'AS IS'. THE MATERIALS MAY
- CONTAIN KNOWN AND UNKNOWN VIOLATIONS OR DEVIATIONS OF INDUSTRY STANDARDS AND SPECIFICATIONS. NVIDIA MAKES NO WARRANTIES, EXPRESSED, IMPLIED, STATUTORY OR OTHERWISE WITH RESPECT TO THE MATERIALS OR OTHERWISE, AND EXPRESSLY DISCLAIMS ALL
- PCB REV
- 83326-A01
- PAGE
- 3 OF 3
- IMPLIED WARRANTIES INCLUDING, WITHOUT LIMITATION, THE WARRANTIES OF DESIGN, OF NONINFRINGEMENT, MERCHANTABILITY OR FITNESS FOR A PARTICULAR PURPOSE, OR ARISING FROM A COURSE OF DEALING, TRADE USAGE, TRADE PRACTICE, OR INDUSTRY STANDARDS.
- BOM REV
- A
- DATE
- dd-mon-year
- A
- B
- C
- D
- E
- F
- G
- H
sheet 2
- A
- B
- C
- D
- E
- F
- G
- H
- BOARD TO BOARD CONNECTOR
- 1
- 1
- 2
- 2
- 3
- 3
- 4
- 4
- 5
- 5
- NVIDIA CORPORATION
- 2701 SAN TOMAS EXPRESSWAY
- ASSEMBLY
- <ASSEMBLY_DESCRIPTION>
- SANTA CLARA, CA 95050, USA
- PAGE DETAIL
- BTB Connector
- NV_PN
- 600-83326-BASE-001
- ALL NVIDIA DESIGN SPECIFICATIONS, REFERENCE SPECIFICATIONS, REFERENCE BOARDS, FILES, DRAWINGS, DIAGNOSTICS, LISTS AND OTHER DOCUMENTS OR INFORMATION (TOGETHER AND SEPARATELY, 'MATERIALS') ARE BEING PROVIDED 'AS IS'. THE MATERIALS MAY
- CONTAIN KNOWN AND UNKNOWN VIOLATIONS OR DEVIATIONS OF INDUSTRY STANDARDS AND SPECIFICATIONS. NVIDIA MAKES NO WARRANTIES, EXPRESSED, IMPLIED, STATUTORY OR OTHERWISE WITH RESPECT TO THE MATERIALS OR OTHERWISE, AND EXPRESSLY DISCLAIMS ALL
- PCB REV
- 83326-A01
- PAGE
- 2 OF 3
- IMPLIED WARRANTIES INCLUDING, WITHOUT LIMITATION, THE WARRANTIES OF DESIGN, OF NONINFRINGEMENT, MERCHANTABILITY OR FITNESS FOR A PARTICULAR PURPOSE, OR ARISING FROM A COURSE OF DEALING, TRADE USAGE, TRADE PRACTICE, OR INDUSTRY STANDARDS.
- BOM REV
- A
- DATE
- dd-mon-year
- A
- B
- C
- D
- E
- F
- G
- H
sheet 3
- A
- B
- C
- D
- E
- F
- G
- H
- P3326-A01
- Jetson TX1/TX2 Developer Kit Camera Module
- With Oscillator
- 1
- 1
- TABLE OF CONTENTS
- Page
- Description
- 1
- Table of Contents
- 2
- BTB Connector
- 3
- Front Camera Connector
- 2
- 2
- 3
- 3
- 4
- 4
- Please get the latest stuff information from BOM sheet(P3326_A01_BOM.xlsx).
- 5
- 5
- NVIDIA CORPORATION
- 2701 SAN TOMAS EXPRESSWAY
- ASSEMBLY
- <ASSEMBLY_DESCRIPTION>
- SANTA CLARA, CA 95050, USA
- PAGE DETAIL
- Table of Contents
- NV_PN
- 600-83326-BASE-001
- ALL NVIDIA DESIGN SPECIFICATIONS, REFERENCE SPECIFICATIONS, REFERENCE BOARDS, FILES, DRAWINGS, DIAGNOSTICS, LISTS AND OTHER DOCUMENTS OR INFORMATION (TOGETHER AND SEPARATELY, 'MATERIALS') ARE BEING PROVIDED 'AS IS'. THE MATERIALS MAY
- CONTAIN KNOWN AND UNKNOWN VIOLATIONS OR DEVIATIONS OF INDUSTRY STANDARDS AND SPECIFICATIONS. NVIDIA MAKES NO WARRANTIES, EXPRESSED, IMPLIED, STATUTORY OR OTHERWISE WITH RESPECT TO THE MATERIALS OR OTHERWISE, AND EXPRESSLY DISCLAIMS ALL
- PCB REV
- 83326-A01
- PAGE
- 1 OF 3
- IMPLIED WARRANTIES INCLUDING, WITHOUT LIMITATION, THE WARRANTIES OF DESIGN, OF NONINFRINGEMENT, MERCHANTABILITY OR FITNESS FOR A PARTICULAR PURPOSE, OR ARISING FROM A COURSE OF DEALING, TRADE USAGE, TRADE PRACTICE, OR INDUSTRY STANDARDS.
- BOM REV
- A
- DATE
- dd-mon-year
- A
- B
- C
- D
- E
- F
- G
- H
